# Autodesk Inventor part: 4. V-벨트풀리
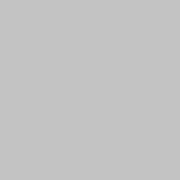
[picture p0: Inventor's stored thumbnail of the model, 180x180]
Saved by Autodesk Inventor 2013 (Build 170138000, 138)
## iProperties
Created: 2015-02
Part Number: 4. V-벨트풀리
Material: 일반
Document SubType Name: Modeling
Designer: Administrator
Density: 1 g/cm^3
Author: Administrator
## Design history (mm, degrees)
